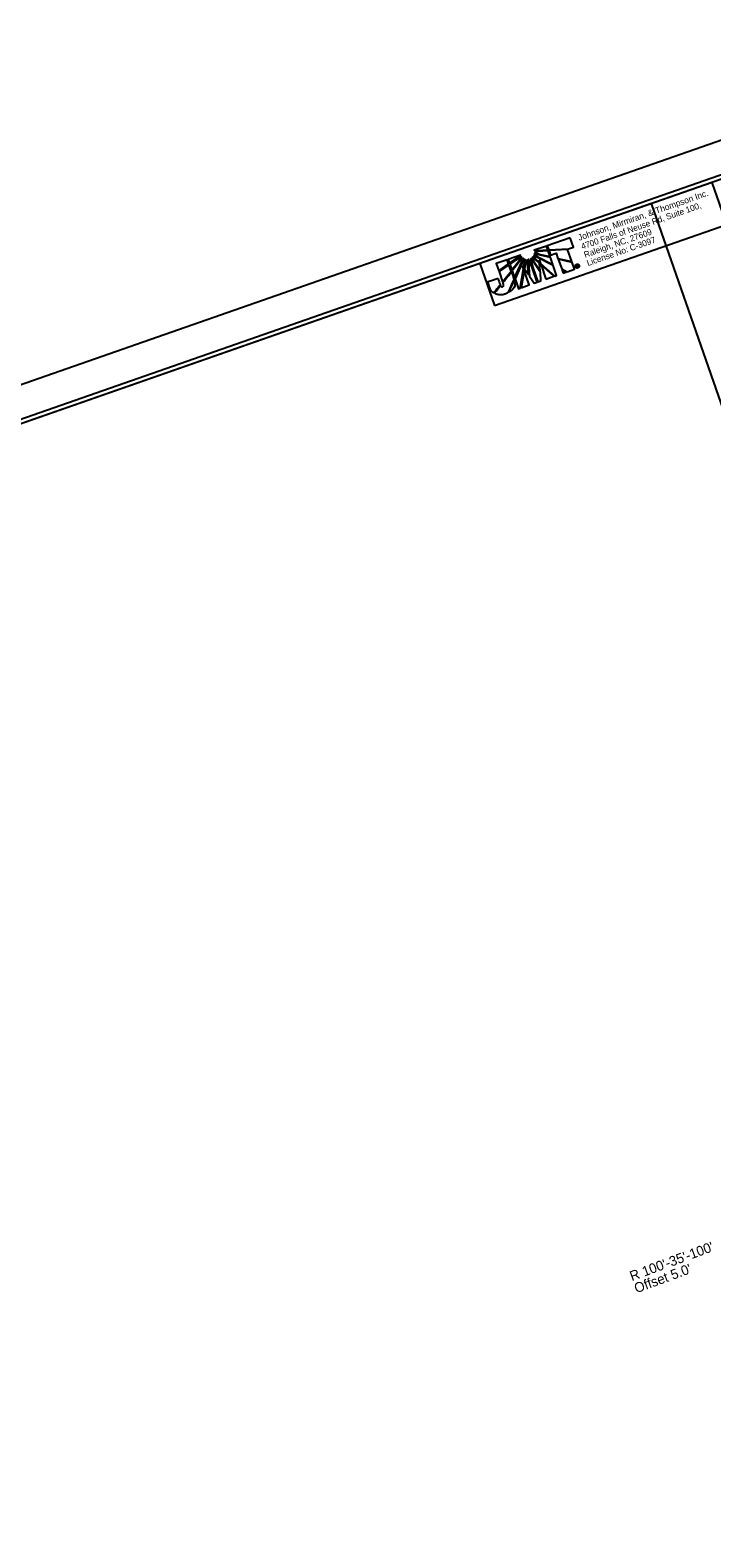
# Model space of a CAD drawing. Extents: x 1721700 to 1723652, y 970581 to 972169.
# Drawn here: x 1722676 to 1723091, y 971251 to 972169 of the extents above; entities that cross this region are included whole.
import ezdxf

# ---------------------------------------------------------------- set-up
doc = ezdxf.new("R2010")
doc.units = 0
for name, color, linetype in [('Prop Dimension', 7, 'Continuous'), ('Prop Dimension Text', 7, 'Continuous'), ('Sheet Clip Boundary CELL', 7, 'Continuous'), ('Sheet Plan CELL', 7, 'Continuous'), ('Sheet Plot Border Inside CELL', 7, 'Continuous'), ('Sheet Plot Border Outside CELL', 7, 'Continuous')]:
    doc.layers.add(name, color=color, linetype=linetype)

msp = doc.modelspace()

# ---------------------------------------------------------------- linework, layer by layer
at = {"layer": 'Prop Dimension Text'}
for p, q in [((1723004.84, 972042.91), (1722990.91, 972038.03)), ((1723006.84, 972037.2), (1723004.84, 972042.91)), ((1722966.48, 972029.43), (1722959.85, 972027.11)), ((1722967.37, 972026.88), (1722966.48, 972029.43)), ((1722974.61, 972032.32), (1722967.15, 972029.71)), ((1722967.15, 972029.71), (1722967.98, 972027.34)), ((1722967.98, 972027.34), (1722973, 972030.81)), ((1722973.18, 972030.3), (1722968.16, 972026.82)), ((1722973, 972030.81), (1722974.61, 972032.32)), ((1722975.26, 972031.32), (1722973.18, 972030.3)), ((1722973.29, 972028.13), (1722975.26, 972031.32)), ((1722976.16, 972030.48), (1722974.09, 972028.32)), ((1722975.51, 972028.24), (1722976.16, 972030.48)), ((1722977.21, 972029.95), (1722975.92, 972027.98)), ((1722977.14, 972027.55), (1722977.21, 972029.95)), ((1722978.37, 972029.7), (1722977.64, 972027.55)), ((1722978.9, 972027.59), (1722978.37, 972029.7)), ((1722979.56, 972029.78), (1722979.4, 972027.34)), ((1722981.68, 972024.66), (1722979.56, 972029.78)), ((1722980.66, 972030.17), (1722982.15, 972024.82)), ((1722982.27, 972028.35), (1722980.66, 972030.17)), ((1722981.61, 972030.83), (1722982.58, 972028.79)), ((1722983.48, 972029.6), (1722981.61, 972030.83)), ((1722982.35, 972031.75), (1722983.9, 972029.91)), ((1722984.58, 972031.01), (1722982.35, 972031.75)), ((1722982.84, 972032.82), (1722984.76, 972031.44)), ((1722985.85, 972032.44), (1722982.84, 972032.82)), ((1722990.41, 972037.82), (1722983.05, 972035.28)), ((1722983.05, 972035.28), (1722985.22, 972035.05)), ((1722985.2, 972034.51), (1722983.06, 972034.05)), ((1722983.06, 972034.05), (1722986.64, 972032.75)), ((1722986.29, 972027.09), (1722983.48, 972029.6)), ((1722983.9, 972029.91), (1722986.24, 972027.78)), ((1722994.54, 972025.88), (1722984.58, 972031.01)), ((1722984.76, 972031.44), (1722994.3, 972026.57)), ((1722991.42, 972034.93), (1722985.2, 972034.51)), ((1722985.22, 972035.05), (1722991.25, 972035.43)), ((1722992.82, 972030.82), (1722985.85, 972032.44)), ((1722986.64, 972032.75), (1722992.61, 972031.41)), ((1722991.25, 972035.43), (1722990.41, 972037.82)), ((1722990.91, 972038.03), (1722991.81, 972035.47)), ((1722992.61, 972031.41), (1722991.42, 972034.93)), ((1722991.81, 972035.47), (1722991.84, 972035.4)), ((1722991.84, 972035.4), (1723003.88, 972036.16)), ((1723003.27, 972035.67), (1722991.97, 972035)), ((1722991.97, 972035), (1722991.99, 972034.96)), ((1722991.99, 972034.96), (1722992.92, 972032.29)), ((1722994.3, 972026.57), (1722992.82, 972030.82)), ((1722992.92, 972032.29), (1722996.33, 972033.48)), ((1722996.33, 972033.48), (1722997.44, 972030.3)), ((1722997.44, 972030.3), (1723005.83, 972028.35)), ((1722997.63, 972029.75), (1722999.71, 972023.83)), ((1723006.01, 972027.84), (1722997.63, 972029.75)), ((1723005.83, 972028.35), (1723003.27, 972035.67)), ((1723003.88, 972036.16), (1723006.84, 972037.2)), ((1722959.85, 972027.11), (1722961.39, 972022.72)), ((1722961.39, 972022.72), (1722967.37, 972026.88)), ((1722967.54, 972026.39), (1722961.57, 972022.21)), ((1722961.57, 972022.21), (1722963.73, 972016.04)), ((1722963.73, 972016.04), (1722968.89, 972022.56)), ((1722968.89, 972022.56), (1722967.54, 972026.39)), ((1722968.16, 972026.82), (1722969.42, 972023.23)), ((1722969.42, 972023.23), (1722973.29, 972028.13)), ((1722974.09, 972028.32), (1722969.62, 972022.66)), ((1722969.62, 972022.66), (1722971.07, 972018.52)), ((1722971.07, 972018.52), (1722975.51, 972028.24)), ((1722975.92, 972027.98), (1722971.32, 972017.82)), ((1722974.52, 972012.19), (1722976.5, 972023.87)), ((1722976.83, 972022.92), (1722975.03, 972012.37)), ((1722976.5, 972023.87), (1722975.89, 972025.62)), ((1722975.89, 972025.62), (1722976.64, 972024.54)), ((1722976.64, 972024.54), (1722977.14, 972027.55)), ((1722979.97, 972014.1), (1722976.83, 972022.92)), ((1722977.64, 972027.55), (1722977.04, 972023.98)), ((1722977.04, 972023.98), (1722979.5, 972020.37)), ((1722979.5, 972020.37), (1722978.9, 972027.59)), ((1722979.4, 972027.34), (1722980.04, 972019.53)), ((1722984.77, 972015.82), (1722981.68, 972024.66)), ((1722982.15, 972024.82), (1722985.24, 972015.99)), ((1722986.72, 972021.75), (1722982.27, 972028.35)), ((1722982.58, 972028.79), (1722986.64, 972022.7)), ((1722986.24, 972027.78), (1722986.12, 972029.21)), ((1722986.12, 972029.21), (1722986.8, 972027.27)), ((1722986.64, 972022.7), (1722986.29, 972027.09)), ((1722987.08, 972016.63), (1722986.72, 972021.75)), ((1722986.8, 972027.27), (1722995.46, 972019.53)), ((1722994.9, 972019.37), (1722987.13, 972026.32)), ((1722987.13, 972026.32), (1722990.15, 972017.71)), ((1722996.63, 972019.94), (1722994.54, 972025.88)), ((1722999.71, 972023.83), (1723002.96, 972022.15)), ((1723002.3, 972021.92), (1722999.93, 972023.18)), ((1722999.93, 972023.18), (1723000.58, 972021.32)), ((1723000.58, 972021.32), (1723002.3, 972021.92)), ((1723002.96, 972022.15), (1723007.45, 972023.73)), ((1723007.45, 972023.73), (1723006.01, 972027.84)), ((1723008.62, 972025.98), (1723009.04, 972026.12)), ((1723008.98, 972024.96), (1723008.62, 972025.98)), ((1723008.83, 972026.72), (1723008.9, 972026.51)), ((1723008.9, 972026.51), (1723008.83, 972026.72)), ((1723009.1, 972025.93), (1723008.92, 972025.86)), ((1723008.92, 972025.86), (1723009, 972025.63)), ((1723009.21, 972025.05), (1723008.98, 972024.96)), ((1723009, 972025.63), (1723009.19, 972025.69)), ((1723009.04, 972026.12), (1723009.1, 972026.15)), ((1723009.04, 972026.12), (1723009.1, 972025.93)), ((1723009.1, 972025.93), (1723009.04, 972026.12)), ((1723009.25, 972025.51), (1723009.07, 972025.44)), ((1723009.07, 972025.44), (1723009.21, 972025.05)), ((1723009.13, 972025.94), (1723009.1, 972025.93)), ((1723009.19, 972025.69), (1723009.25, 972025.51)), ((1723009.25, 972025.51), (1723009.19, 972025.69)), ((1723009.19, 972025.69), (1723009.2, 972025.69)), ((1723009.26, 972025.51), (1723009.25, 972025.51)), ((1723009.53, 972024.71), (1723009.54, 972024.72)), ((1723009.53, 972024.71), (1723009.61, 972024.49)), ((1723009.61, 972024.49), (1723009.53, 972024.71)), ((1723009.62, 972024.5), (1723009.61, 972024.49)), ((1722971.32, 972017.82), (1722973.42, 972011.81)), ((1722973.42, 972011.81), (1722974.52, 972012.19)), ((1722975.03, 972012.37), (1722979.97, 972014.1)), ((1722980.04, 972019.53), (1722982.96, 972015.18)), ((1722982.96, 972015.18), (1722984.77, 972015.82)), ((1722985.24, 972015.99), (1722987.08, 972016.63)), ((1722990.15, 972017.71), (1722994.9, 972019.37)), ((1722995.46, 972019.53), (1722996.63, 972019.94))]:
    msp.add_line(p, q, dxfattribs=at)
msp.add_lwpolyline([(1722958.72, 972001.56), (1723100.36, 972051.02), (1723091.43, 972076.58), (1722949.79, 972027.12)], close=True, dxfattribs=at)
for points in [[(1723004.84, 972042.91), (1722990.91, 972038.03), (1722991.81, 972035.47), (1722991.84, 972035.4), (1723003.88, 972036.16), (1723006.84, 972037.2), (1723004.84, 972042.91)], [(1722961.39, 972022.72), (1722967.37, 972026.88), (1722966.48, 972029.43), (1722959.85, 972027.11), (1722961.39, 972022.72)], [(1722973, 972030.81), (1722974.61, 972032.32), (1722967.15, 972029.71), (1722967.98, 972027.34), (1722973, 972030.81)], [(1722968.16, 972026.82), (1722969.42, 972023.23), (1722973.29, 972028.13), (1722975.26, 972031.32), (1722973.18, 972030.3), (1722968.16, 972026.82)], [(1722969.62, 972022.66), (1722971.07, 972018.52), (1722975.51, 972028.24), (1722976.16, 972030.48), (1722974.09, 972028.32), (1722969.62, 972022.66)], [(1722977.21, 972029.95), (1722975.92, 972027.98), (1722971.32, 972017.82), (1722973.42, 972011.81), (1722974.52, 972012.19), (1722976.5, 972023.87), (1722975.89, 972025.62), (1722976.64, 972024.54), (1722977.14, 972027.55), (1722977.21, 972029.95)], [(1722978.37, 972029.7), (1722977.64, 972027.55), (1722977.04, 972023.98), (1722979.5, 972020.37), (1722978.9, 972027.59), (1722978.37, 972029.7)], [(1722979.4, 972027.34), (1722980.04, 972019.53), (1722982.96, 972015.18), (1722984.77, 972015.82), (1722981.68, 972024.66), (1722979.56, 972029.78), (1722979.4, 972027.34)], [(1722980.66, 972030.17), (1722982.15, 972024.82), (1722985.24, 972015.99), (1722987.08, 972016.63), (1722986.72, 972021.75), (1722982.27, 972028.35), (1722980.66, 972030.17)], [(1722981.61, 972030.83), (1722982.58, 972028.79), (1722986.64, 972022.7), (1722986.29, 972027.09), (1722983.48, 972029.6), (1722981.61, 972030.83)], [(1722982.35, 972031.75), (1722983.9, 972029.91), (1722986.24, 972027.78), (1722986.12, 972029.21), (1722986.8, 972027.27), (1722995.46, 972019.53), (1722996.63, 972019.94), (1722994.54, 972025.88), (1722984.58, 972031.01), (1722982.35, 972031.75)], [(1722982.84, 972032.82), (1722984.76, 972031.44), (1722994.3, 972026.57), (1722992.82, 972030.82), (1722985.85, 972032.44), (1722982.84, 972032.82)], [(1722985.22, 972035.05), (1722991.25, 972035.43), (1722990.41, 972037.82), (1722983.05, 972035.28), (1722985.22, 972035.05)], [(1722983.06, 972034.05), (1722986.64, 972032.75), (1722992.61, 972031.41), (1722991.42, 972034.93), (1722985.2, 972034.51), (1722983.06, 972034.05)], [(1722991.97, 972035), (1722991.99, 972034.96), (1722992.92, 972032.29), (1722996.33, 972033.48), (1722997.44, 972030.3), (1723005.83, 972028.35), (1723003.27, 972035.67), (1722991.97, 972035)], [(1722997.63, 972029.75), (1722999.71, 972023.83), (1723002.96, 972022.15), (1723007.45, 972023.73), (1723006.01, 972027.84), (1722997.63, 972029.75), (1722997.63, 972029.75)], [(1722963.73, 972016.04), (1722968.89, 972022.56), (1722967.54, 972026.39), (1722961.57, 972022.21), (1722963.73, 972016.04)], [(1722975.03, 972012.37), (1722979.97, 972014.1), (1722976.83, 972022.92), (1722975.03, 972012.37)], [(1722990.15, 972017.71), (1722994.9, 972019.37), (1722987.13, 972026.32), (1722990.15, 972017.71)], [(1723000.58, 972021.32), (1723000.58, 972021.32), (1723002.3, 972021.92), (1722999.93, 972023.18), (1723000.58, 972021.32)], [(1723009.75, 972025.5), (1723009.77, 972025.45), (1723009.79, 972025.41), (1723009.8, 972025.38), (1723009.87, 972025.28), (1723009.66, 972025.2)]]:
    msp.add_lwpolyline(points, dxfattribs=at)
for points, degree in [([(1722963.72, 972013.02), (1722963.32, 972012.89), (1722962.91, 972012.99), (1722962.51, 972013.67), (1722962.51, 972013.67), (1722958.78, 972009.06), (1722958.78, 972009.06), (1722960.79, 972008.03), (1722963.45, 972007.93), (1722965.43, 972008.63), (1722965.94, 972008.81), (1722966.32, 972008.99), (1722966.83, 972009.29), (1722966.83, 972009.29), (1722970.64, 972017.55), (1722970.64, 972017.55), (1722970.64, 972017.55), (1722969.08, 972022.01), (1722969.08, 972022.01), (1722969.08, 972022.01), (1722963.93, 972015.48), (1722963.93, 972015.48), (1722964.51, 972013.81), (1722964.26, 972013.22), (1722963.72, 972013.02)], 3), ([(1722963.72, 972013.02), (1722963.32, 972012.89), (1722962.91, 972012.99), (1722962.51, 972013.67), (1722962.51, 972013.67), (1722958.78, 972009.06), (1722958.78, 972009.06), (1722960.79, 972008.03), (1722963.45, 972007.93), (1722965.43, 972008.63), (1722965.94, 972008.81), (1722966.32, 972008.99), (1722966.83, 972009.29), (1722966.83, 972009.29), (1722970.64, 972017.55), (1722970.64, 972017.55), (1722970.64, 972017.55), (1722969.08, 972022.01), (1722969.08, 972022.01), (1722969.08, 972022.01), (1722963.93, 972015.48), (1722963.93, 972015.48), (1722964.51, 972013.81), (1722964.26, 972013.22), (1722963.72, 972013.02)], 3), ([(1723009.61, 972024.49), (1723009.3, 972024.39), (1723009, 972024.4), (1723008.7, 972024.55), (1723008.4, 972024.68), (1723008.2, 972024.91), (1723008.09, 972025.22), (1723007.98, 972025.54), (1723008, 972025.84), (1723008.15, 972026.12), (1723008.29, 972026.41), (1723008.51, 972026.61), (1723008.83, 972026.72)], 3), ([(1723008.9, 972026.51), (1723008.65, 972026.42), (1723008.47, 972026.27), (1723008.35, 972026.04), (1723008.24, 972025.8), (1723008.22, 972025.55), (1723008.31, 972025.3), (1723008.4, 972025.05), (1723008.57, 972024.86), (1723008.8, 972024.75), (1723009.04, 972024.64), (1723009.28, 972024.63), (1723009.53, 972024.71)], 3), ([(1723008.83, 972026.72), (1723009.14, 972026.83), (1723009.45, 972026.81), (1723009.74, 972026.68), (1723010.03, 972026.55), (1723010.24, 972026.33), (1723010.35, 972026.01)], 3), ([(1723009.54, 972024.72), (1723009.79, 972024.8), (1723009.97, 972024.96), (1723010.08, 972025.2), (1723010.2, 972025.43), (1723010.21, 972025.69), (1723010.13, 972025.94), (1723010.04, 972026.18), (1723009.87, 972026.37), (1723009.63, 972026.49), (1723009.4, 972026.59), (1723009.16, 972026.6), (1723008.9, 972026.51)], 3), ([(1723009.1, 972026.15), (1723009.36, 972026.24), (1723009.52, 972026.18), (1723009.59, 972025.98), (1723009.63, 972025.88), (1723009.62, 972025.8), (1723009.55, 972025.71)], 3), ([(1723009.2, 972025.69), (1723009.34, 972025.74), (1723009.4, 972025.82), (1723009.37, 972025.9), (1723009.35, 972025.97), (1723009.27, 972025.99), (1723009.13, 972025.94)], 3), ([(1723009.45, 972025.53), (1723009.42, 972025.54), (1723009.35, 972025.54), (1723009.26, 972025.51)], 2), ([(1723009.66, 972025.2), (1723009.61, 972025.25), (1723009.57, 972025.3), (1723009.55, 972025.37), (1723009.52, 972025.46), (1723009.49, 972025.52), (1723009.45, 972025.53)], 3), ([(1723009.55, 972025.71), (1723009.63, 972025.7), (1723009.69, 972025.63), (1723009.75, 972025.5)], 2), ([(1723010.35, 972026.01), (1723010.46, 972025.7), (1723010.44, 972025.39), (1723010.3, 972025.1), (1723010.16, 972024.81), (1723009.93, 972024.61), (1723009.62, 972024.5)], 3), ([(1722960.83, 972018.21), (1722960.83, 972018.21), (1722954.7, 972016.06), (1722954.7, 972016.06), (1722954.7, 972016.06), (1722956.04, 972012.23), (1722956.04, 972012.23), (1722956.04, 972012.23), (1722956.18, 972011.82), (1722956.18, 972011.82), (1722956.6, 972010.62), (1722957.33, 972009.81), (1722958.31, 972009.25), (1722958.31, 972009.25), (1722962.28, 972014.08), (1722962.25, 972014.16), (1722962.25, 972014.16), (1722960.83, 972018.21), (1722960.83, 972018.21)], 3), ([(1722970.88, 972016.85), (1722970.88, 972016.85), (1722967.59, 972009.72), (1722967.59, 972009.72), (1722969.9, 972011.22), (1722971.83, 972013.78), (1722970.88, 972016.85)], 3)]:
    msp.add_open_spline(points, degree=degree, dxfattribs=at)
at = {"layer": 'Sheet Clip Boundary CELL'}
for points in [[(1723600.74, 971158.62), (1723483.33, 971374.55), (1723099.98, 972079.55), (1721911.36, 971664.47), (1722084.53, 971168.86), (1722257.61, 970673.21), (1723579.34, 971134.77)], [(1723600.74, 971158.62), (1723483.33, 971374.55), (1723099.98, 972079.55), (1721911.36, 971664.47), (1722084.53, 971168.86), (1722257.61, 970673.21), (1723579.34, 971134.77)], [(1722257.53, 970673.18), (1723579.27, 971134.74), (1723302.82, 971926.38), (1723124.14, 971863.98), (1723054.41, 972063.64), (1721911.36, 971664.47)]]:
    msp.add_lwpolyline(points, close=True, dxfattribs=at)
at = {"layer": 'Sheet Plan CELL'}
msp.add_lwpolyline([(1723280.32, 972142.53), (1721864.15, 971647.99), (1722210.32, 970656.69), (1723626.47, 971151.23)], close=True, dxfattribs=at)
at = {"layer": 'Sheet Plot Border Inside CELL'}
msp.add_lwpolyline([(1722066.24, 970603.72), (1723639.08, 971152.98), (1723291.28, 972148.99), (1721718.43, 971599.74)], close=True, dxfattribs=at)
at = {"layer": 'Sheet Plot Border Outside CELL'}
msp.add_lwpolyline([(1722060.57, 970580.55), (1723649.94, 971135.58), (1723288.94, 972169.36), (1721699.56, 971614.33)], close=True, dxfattribs=at)

# ---------------------------------------------------------------- texts
at = {"layer": 'Prop Dimension'}
for s, p in [("R 100'-35'-100' ", (1723042.52, 971407.06)), ("Offset 5.0'", (1723045.24, 971399.68))]:
    msp.add_text(s, height=6, rotation=20.24972, dxfattribs=at).set_placement(p)
at = {"layer": 'Prop Dimension Text'}
for s, height, p in [('Johnson, Mirmiran, & Thompson Inc.', 3.8334, (1723010.41, 972040.94)), ('4700 Falls of Neuse Rd, Suite 100, ', 3.7239, (1723012.26, 972035.63)), ('Raleigh, NC, 27609', 3.7239, (1723014.02, 972030.61)), ('License No: C-3097', 3.7239, (1723015.77, 972025.58))]:
    msp.add_text(s, height=height, rotation=19.24972, dxfattribs=at).set_placement(p)

doc.saveas('drawing.dxf')
